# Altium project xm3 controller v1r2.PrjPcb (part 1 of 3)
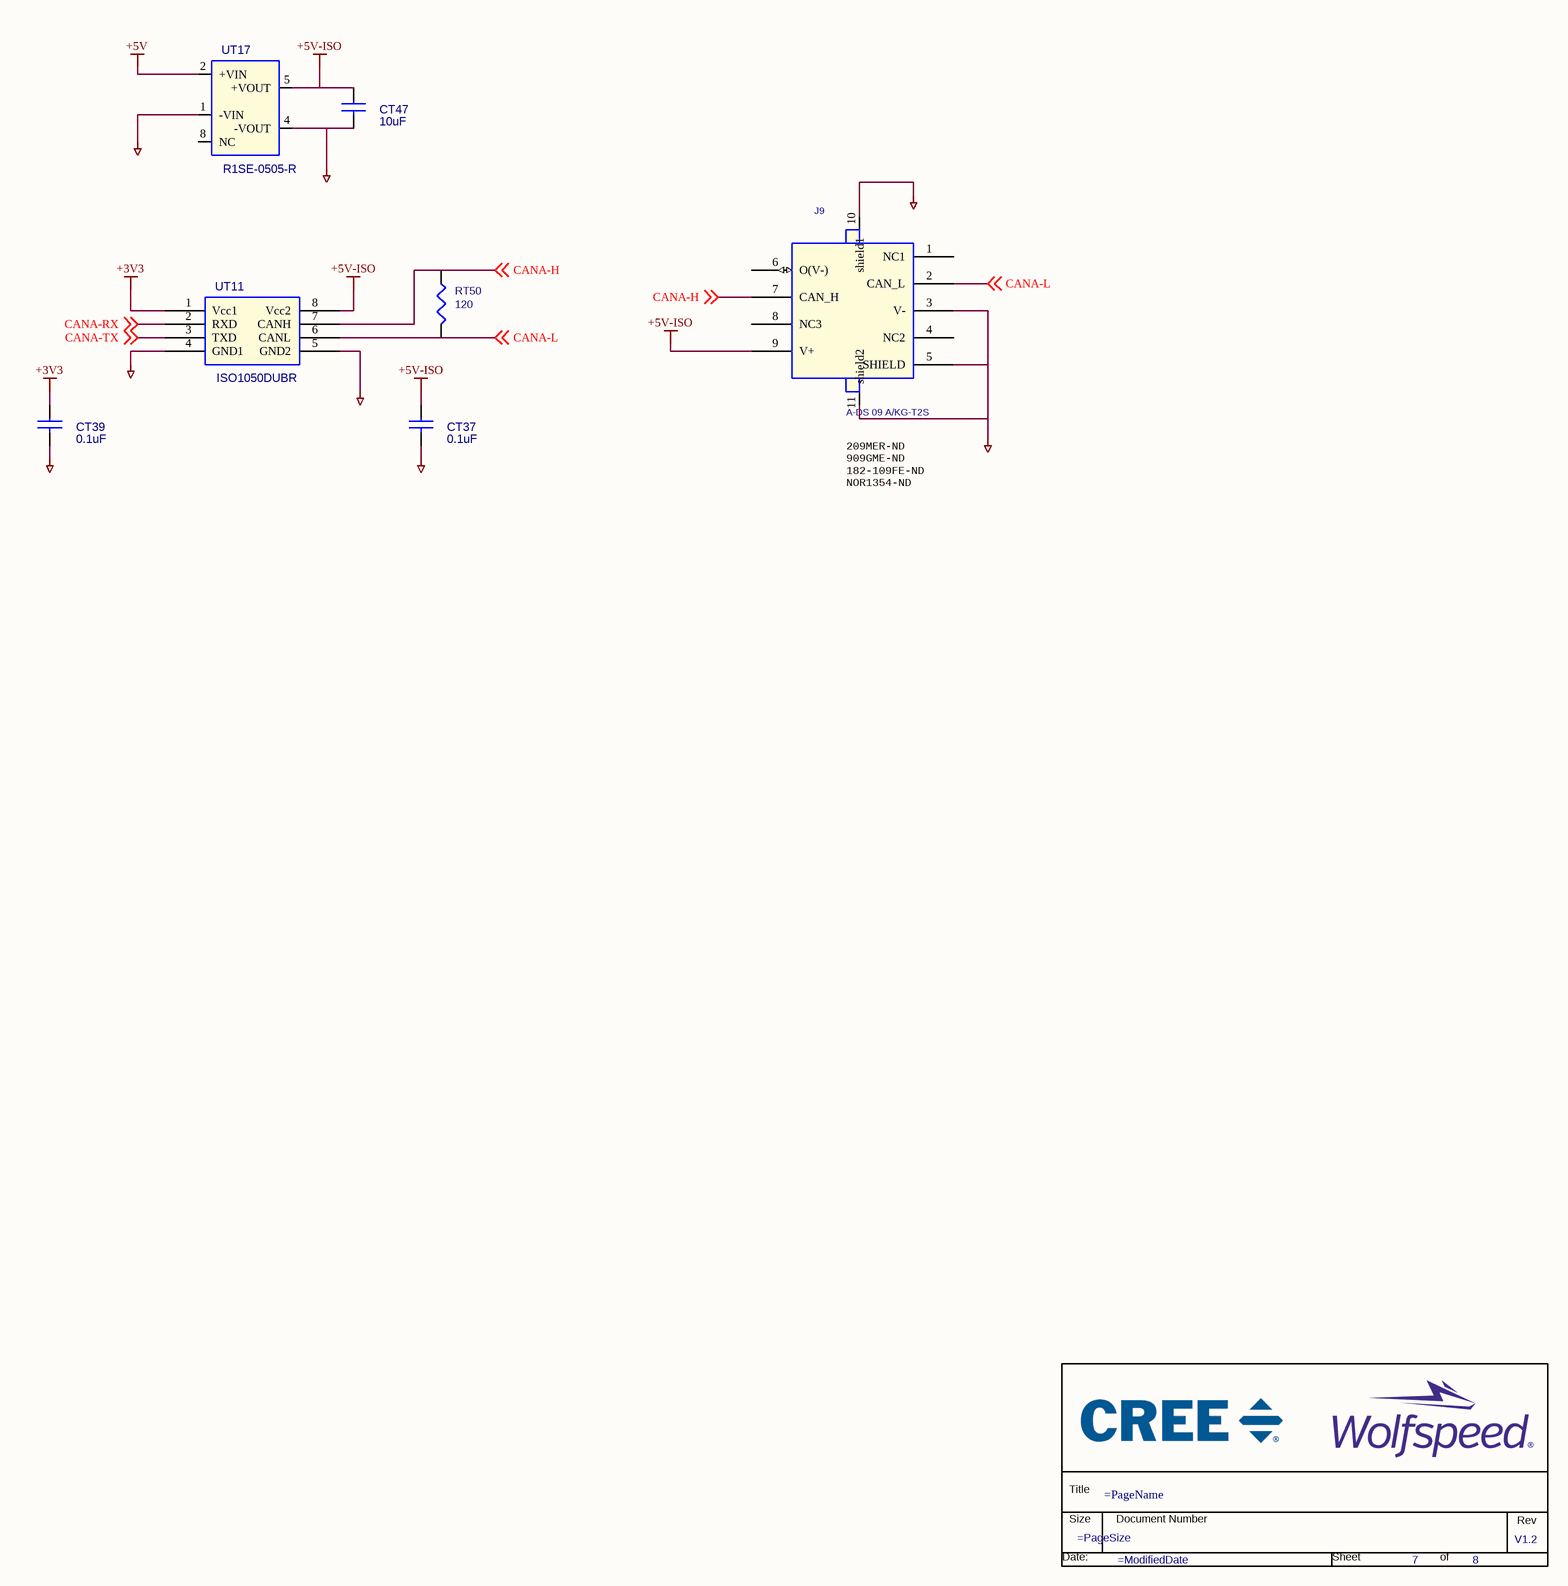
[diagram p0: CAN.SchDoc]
8 sheets, 370 parts. Net scope: global (net labels, ports and power ports of the same name join across sheets).
Board file: XM3-Controller-V1R2-1.PcbDoc
Sheets:
  CAN.SchDoc
  Current Sensors.SchDoc
  Gate Driver Interface.SchDoc
  LAUNCHPAD.SchDoc
  Power Supply.SchDoc
  Revision History.SchDoc
  Temperature Sense.SchDoc
  Voltage Sense.SchDoc

## Sheet CAN.SchDoc: Controller
size 492 x 365 mm; OrgAddr3: USA; Page Create Date: March  8, 1995; OrgName: Wolfspeed; OrgAddr1: 535 W Research Center Blvd.; Page Number: 7; Page Size: A; Comment: DualBrandTitleBlock1; Page Count: 8; OrgAddr2: Fayetteville, AR, 72701; Page Name: CAN; RevCode: V1.2; DsnPath: C:\Users\cnew\Downloads\xm3 controller v1r2-2022-03-14T15-49\xm3 controller v1r2.dsn; SchematicName: SCHEMATIC1; PageName: CAN; PageSize: A; TopSchematic: True

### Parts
(Parts that share a designator on the sheet are numbered #1, #2 ... from top to bottom, then left to right.)
*#1  Page Count: 8  Page Number: 7  RevCode: V1.2  (hidden comment: DualBrandTitleBlock1)  (graphical)
CT37  0.1uF  [CAPC1608X87N]
CT39  0.1uF  [CAPC1608X87N]
CT47  10uF  [CAPC2012X135N]
J9  A-DS 09 A/KG-T2S  [DB9]
RT50  120  [RESC1608X55N]
UT11  ISO1050DUBR  [SMD-8_gull_wing_V2]
UT17  R1SE-0505-R  [8-SMD-5leads]

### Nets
0: CT39.2 UT11.4(GND1) UT17.1(-VIN)
1: CT37.2 CT47.2 J9.3(V-) J9.5(SHIELD) J9.10(shield1) J9.11(shield2) UT11.5(GND2) UT17.4(-VOUT)
+3V3: CT39.1 UT11.1(Vcc1)
+5V: UT17.2(+VIN)
+5V-ISO: CT37.1 CT47.1 J9.9(V+) UT11.8(Vcc2) UT17.5(+VOUT)
CANA-H: J9.7(CAN_H) RT50.1 UT11.7(CANH) ; off-sheet CANA-H
CANA-L: J9.2(CAN_L) RT50.2 UT11.6(CANL) ; off-sheet CANA-L
CANA-RX: UT11.2(RXD) ; off-sheet CANA-RX
CANA-TX: UT11.3(TXD) ; off-sheet CANA-TX

Not connected (* = marked no-connect by the designer): J9 1(NC1) 4(NC2) 6(O(V-)) 8(NC3); UT17 8(NC)

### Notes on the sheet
- (near J9) 209MER-ND
  909GME-ND
  182-109FE-ND
  NOR1354-ND

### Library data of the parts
*#1 = DualBrandTitleBlock1: OrgAddr3: USA; OrgAddr2: Fayetteville, AR, 72701; OrgAddr1: 535 W Research Center Blvd.; OrgName: Wolfspeed; Title: Controller
CT37 = CAP: CAP CER 0.1UF 25V X7R 0603; Part Reference: CT37; Manufacturer PN: C0603C104K3RACTU; Manufacturer: Kemet; PART_NUMBER: TMP-847; Company Part Status: New; CLASS: DISCRETE; Tolerance: 10%; Dielectric Type: Capacitors
CT39 = CAP: CAP CER 0.1UF 25V X7R 0603; Part Reference: CT39; Manufacturer PN: C0603C104K3RACTU; Manufacturer: Kemet; PART_NUMBER: TMP-847; Company Part Status: New; CLASS: DISCRETE; Tolerance: 10%; Dielectric Type: Capacitors
CT47 = CAP: CAP CER 10UF 25V X7S 0805; Part Reference: CT47; Manufacturer: Murata Electronics North America; Manufacturer PN: GRM21BC71E106KE11L; Company Part Status: New; Dielectric Type: Capacitors; Tolerance: 10%; CLASS: DISCRETE
J9 = DSUB - NI CAN Interface_0: CONN D-SUB PLUG 9POS R/A SOLDER; Part Reference: J9; Manufacturer: Assmann WSW Components; Company Part Status: New; CLASS: IO
RT50 = R: RES SMD 120 OHM 5% 1/10W 0603; Part Reference: RT50; PART_NUMBER: TMP-619; Manufacturer: Yageo; Manufacturer PN: RC0603JR-07120RL; Company Part Status: New; Temperature Coefficient: 100ppm/C; Rated Power: 0.1W, 1/10W; CLASS: DISCRETE
UT11 = ISO1050DUB: IC TXRX CAN 5V 8SOP; Part Reference: UT11; PART_NUMBER: TMP-237; Manufacturer: Texas Instruments; Company Part Status: New; Supply Voltage: 3 V - 5.5 V
UT17 = R1se-0505-R: DC/DC CONVERTER 1W 5VIN 5VOUT; Part Reference: UT17; PART_NUMBER: TMP-302; Manufacturer: Recom Power; Company Part Status: New; CLASS: IC

## Sheet Current Sensors.SchDoc: Controller
size 492 x 365 mm; OrgAddr3: USA; Page Create Date: March  8, 1995; OrgName: Wolfspeed; OrgAddr1: 535 W Research Center Blvd.; Page Number: 3; Page Size: A; Comment: DualBrandTitleBlock1; Page Count: 8; OrgAddr2: Fayetteville, AR, 72701; Page Name: Current Sensors; RevCode: V1.2; DsnPath: C:\Users\cnew\Downloads\xm3 controller v1r2-2022-03-14T15-49\xm3 controller v1r2.dsn; SchematicName: SCHEMATIC1; PageName: Current Sensors; PageSize: A; TopSchematic: True
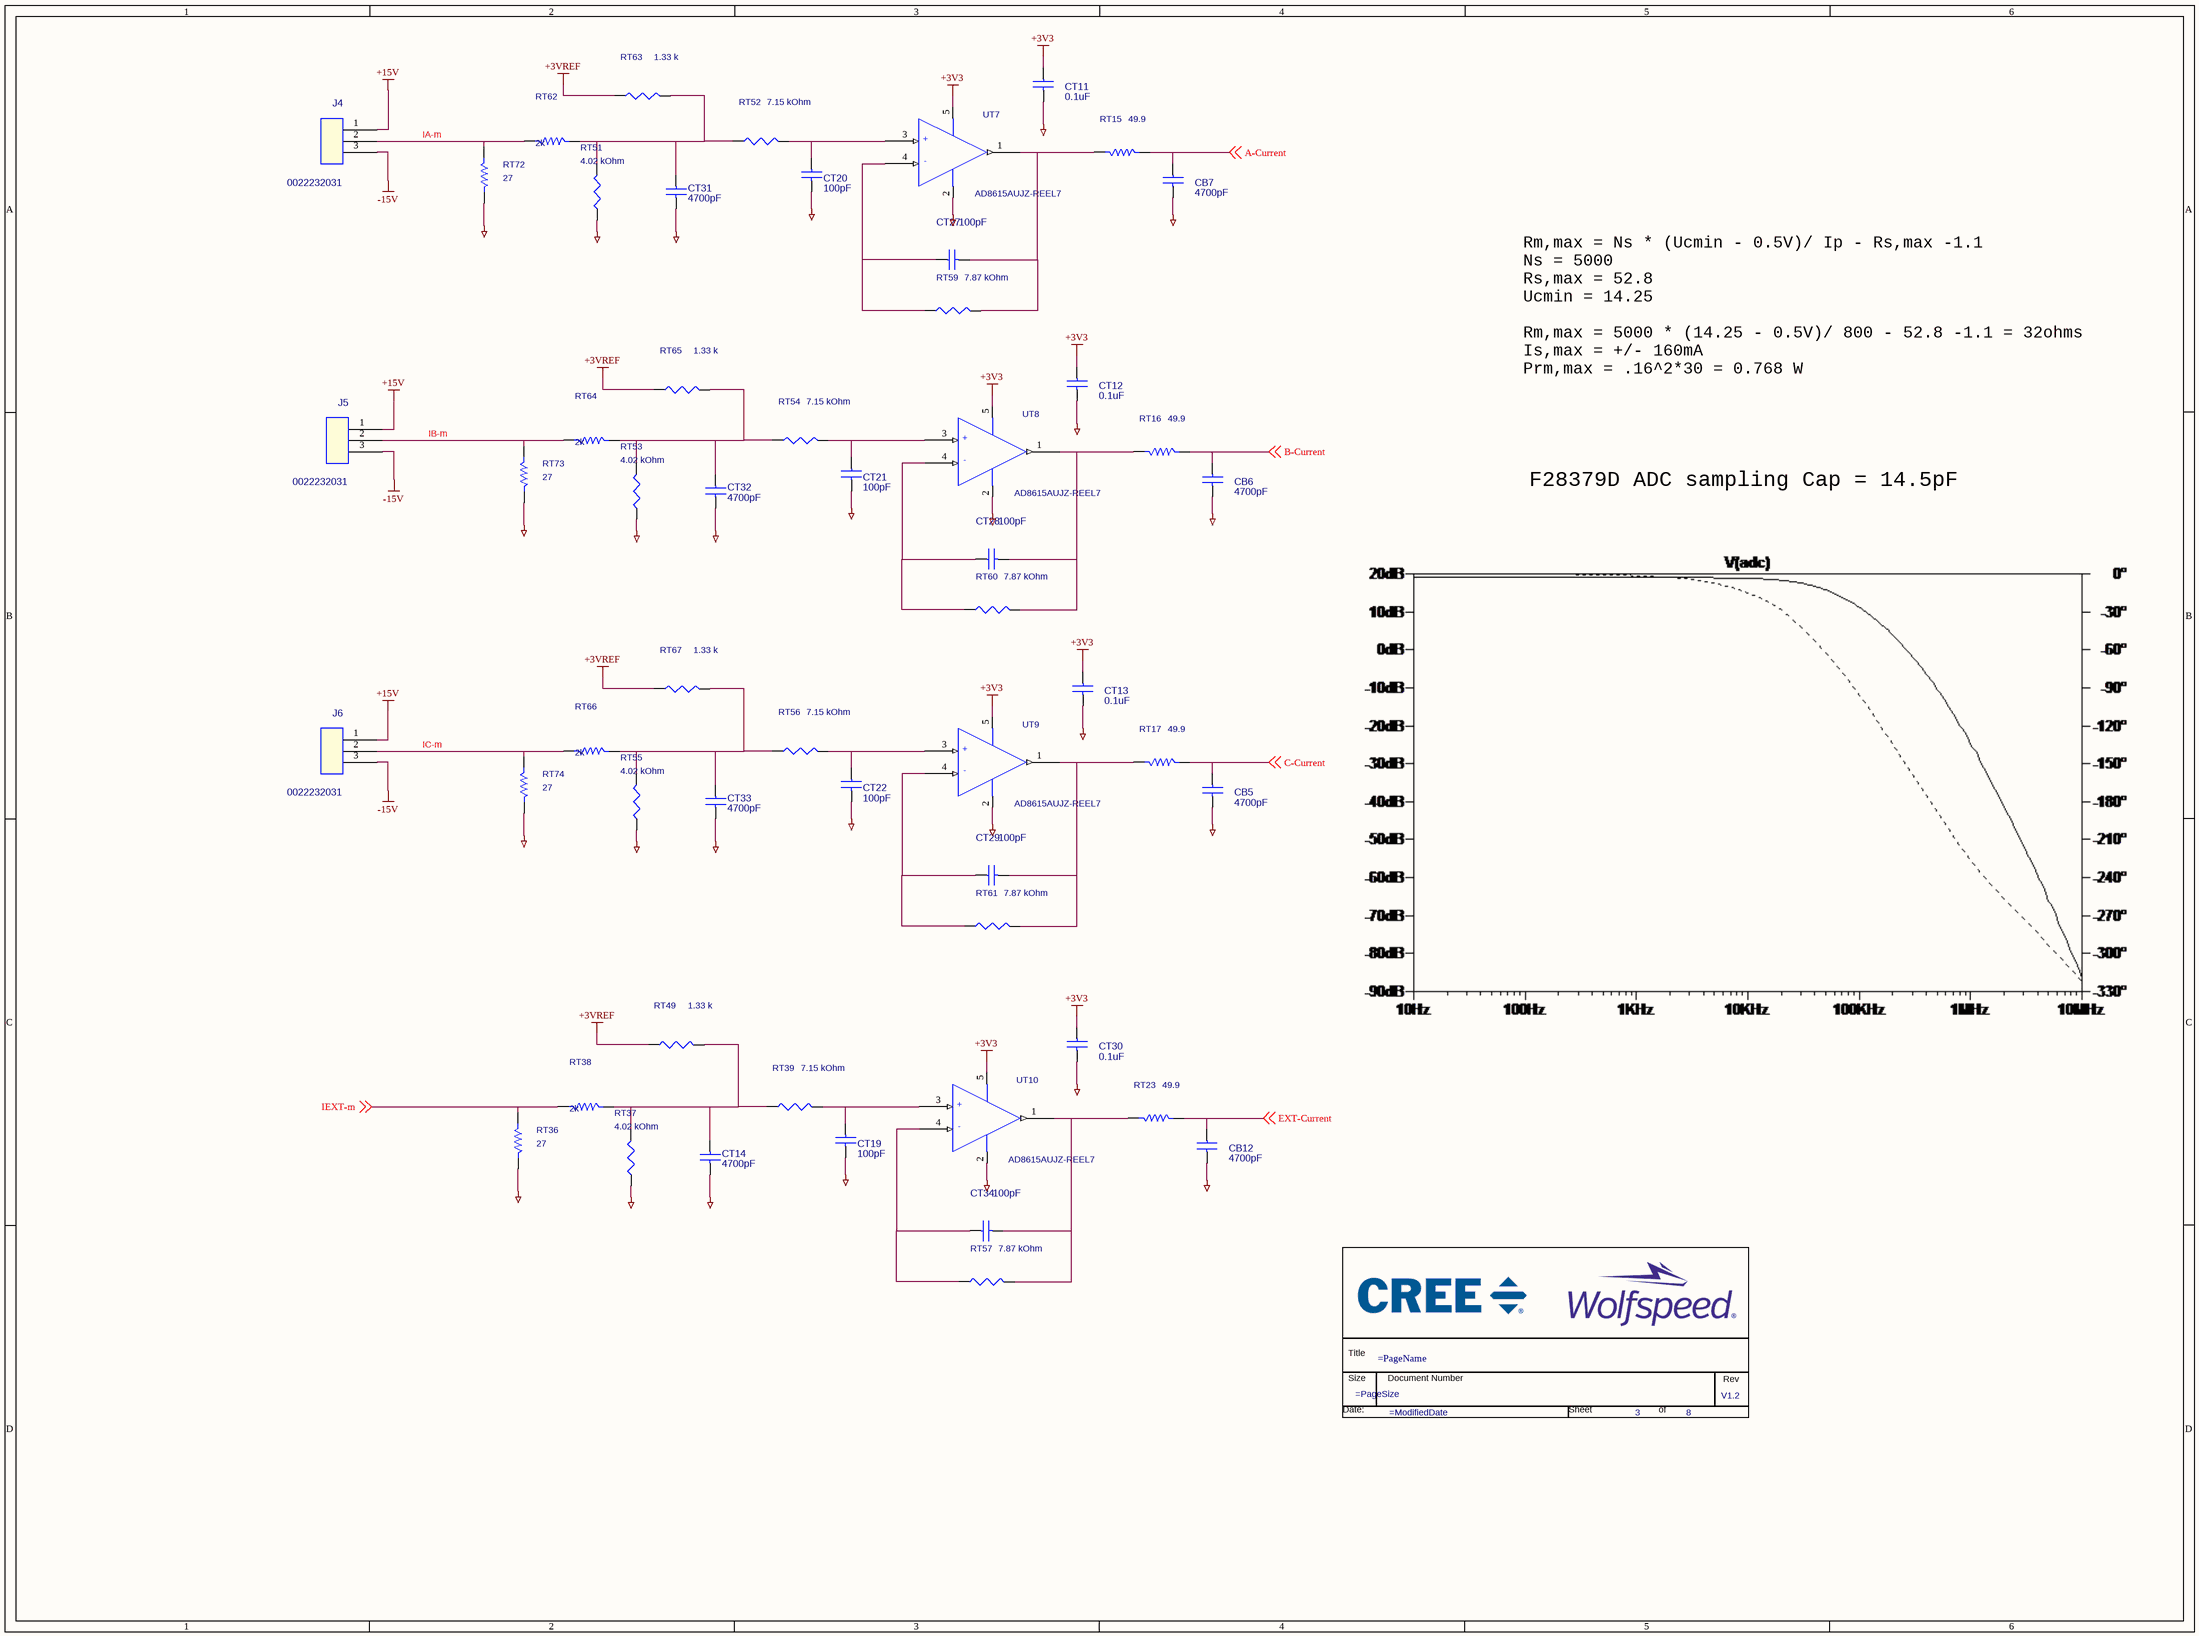
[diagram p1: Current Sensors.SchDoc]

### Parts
(Parts that share a designator on the sheet are numbered #1, #2 ... from top to bottom, then left to right.)
*#2  Page Count: 8  Page Number: 3  RevCode: V1.2  (hidden comment: DualBrandTitleBlock1)  (graphical)
CB5  4700pF  [c_0603]
CB6  4700pF  [c_0603]
CB7  4700pF  [c_0603]
CB12  4700pF  [c_0603]
CT11  0.1uF  [CAPC1608X87N]
CT12  0.1uF  [CAPC1608X87N]
CT13  0.1uF  [CAPC1608X87N]
CT14  4700pF  [c_0603]
CT19  100pF  [CAPC1608X90N]
CT20  100pF  [CAPC1608X90N]
CT21  100pF  [CAPC1608X90N]
CT22  100pF  [CAPC1608X90N]
CT27  100pF  [CAPC1608X90N]
CT28  100pF  [CAPC1608X90N]
CT29  100pF  [CAPC1608X90N]
CT30  0.1uF  [CAPC1608X87N]
CT31  4700pF  [c_0603]
CT32  4700pF  [c_0603]
CT33  4700pF  [c_0603]
CT34  100pF  [CAPC1608X90N]
J4  0022232031  [CON_1x3_vert_lock]
J5  0022232031  [CON_1x3_vert_lock]
J6  0022232031  [CON_1x3_vert_lock]
RT15  49.9  [RESC1608X55N]
RT16  49.9  [RESC1608X55N]
RT17  49.9  [RESC1608X55N]
RT23  49.9  [RESC1608X55N]
RT36  27  [RESC3216X65N]
RT37  4.02 kOhm  [RESC1608X55N]
RT38  2k  [RESC1608X55N]
RT39  7.15 kOhm  [RESC1608X55N]
RT49  1.33 k  [RESC1608X55N]
RT51  4.02 kOhm  [RESC1608X55N]
RT52  7.15 kOhm  [RESC1608X55N]
RT53  4.02 kOhm  [RESC1608X55N]
RT54  7.15 kOhm  [RESC1608X55N]
RT55  4.02 kOhm  [RESC1608X55N]
RT56  7.15 kOhm  [RESC1608X55N]
RT57  7.87 kOhm  [RESC1608X55N]
RT59  7.87 kOhm  [RESC1608X55N]
RT60  7.87 kOhm  [RESC1608X55N]
RT61  7.87 kOhm  [RESC1608X55N]
RT62  2k  [RESC1608X55N]
RT63  1.33 k  [RESC1608X55N]
RT64  2k  [RESC1608X55N]
RT65  1.33 k  [RESC1608X55N]
RT66  2k  [RESC1608X55N]
RT67  1.33 k  [RESC1608X55N]
RT72  27  [RESC3216X65N]
RT73  27  [RESC3216X65N]
RT74  27  [RESC3216X65N]
UT7  AD8615AUJZ-REEL7  [sot23-5_0_95x2_70p_h1_22]
UT8  AD8615AUJZ-REEL7  [sot23-5_0_95x2_70p_h1_22]
UT9  AD8615AUJZ-REEL7  [sot23-5_0_95x2_70p_h1_22]
UT10  AD8615AUJZ-REEL7  [sot23-5_0_95x2_70p_h1_22]

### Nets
0: CB5.2 CB6.2 CB7.2 CB12.2 CT11.2 CT12.2 CT13.2 CT14.2 CT19.2 CT20.2 CT21.2 CT22.2 CT30.2 CT31.2 CT32.2 CT33.2 RT36.2 RT37.1 RT51.1 RT53.1 RT55.1 RT72.2 RT73.2 RT74.2 UT7.2(V-) UT8.2(V-) UT9.2(V-) UT10.2(V-)
+3V3: CT11.1 CT12.1 CT13.1 CT30.1 UT7.5(V+) UT8.5(V+) UT9.5(V+) UT10.5(V+)
+3VREF: RT49.1 RT63.1 RT65.1 RT67.1
+15V: J4.1 J5.1 J6.1
-15V: J4.3 J5.3 J6.3
A-Current: CB7.1 RT15.2 ; off-sheet A-Current
B-Current: CB6.1 RT16.2 ; off-sheet B-Current
C-Current: CB5.1 RT17.2 ; off-sheet C-Current
EXT-Current: CB12.1 RT23.2 ; off-sheet EXT-Current
IA-m: J4.2 RT62.1 RT72.1
IB-m: J5.2 RT64.1 RT73.1
IC-m: J6.2 RT66.1 RT74.1
IEXT-m: RT36.1 RT38.1 ; off-sheet IEXT-m
NetCT14_1: CT14.1 RT37.2 RT38.2 RT39.1 RT49.2
NetCT19_1: CT19.1 RT39.2 UT10.3(IN+)
NetCT20_1: CT20.1 RT52.2 UT7.3(IN+)
NetCT21_1: CT21.1 RT54.2 UT8.3(IN+)
NetCT22_1: CT22.1 RT56.2 UT9.3(IN+)
NetCT27_1: CT27.1 RT59.1 UT7.4(IN-)
NetCT27_2: CT27.2 RT15.1 RT59.2 UT7.1(OUT)
NetCT28_1: CT28.1 RT60.1 UT8.4(IN-)
NetCT28_2: CT28.2 RT16.1 RT60.2 UT8.1(OUT)
NetCT29_1: CT29.1 RT61.1 UT9.4(IN-)
NetCT29_2: CT29.2 RT17.1 RT61.2 UT9.1(OUT)
NetCT31_1: CT31.1 RT51.2 RT52.1 RT62.2 RT63.2
NetCT32_1: CT32.1 RT53.2 RT54.1 RT64.2 RT65.2
NetCT33_1: CT33.1 RT55.2 RT56.1 RT66.2 RT67.2
NetCT34_1: CT34.1 RT57.1 UT10.4(IN-)
NetCT34_2: CT34.2 RT23.1 RT57.2 UT10.1(OUT)

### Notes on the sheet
- Rm,max = Ns * (Ucmin - 0.5V)/ Ip - Rs,max -1.1
  Ns = 5000
  Rs,max = 52.8
  Ucmin = 14.25
- Rm,max = 5000 * (14.25 - 0.5V)/ 800 - 52.8 -1.1 = 32ohms
  Is,max = +/- 160mA
  Prm,max = .16^2*30 = 0.768 W
- F28379D ADC sampling Cap = 14.5pF

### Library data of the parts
*#2 = DualBrandTitleBlock1: as *#1 on sheet CAN
CB5 = CAP: CAP CER 4700PF 25V X7R 0603; Part Reference: CB5; Manufacturer PN: GCM188R71E472KA37D; Manufacturer: Murata Electronics North America; PART_NUMBER: TMP-889; Company Part Status: New; CLASS: DISCRETE; Tolerance: 10%; Dielectric Type: Capacitors
CB6 = CAP: CAP CER 4700PF 25V X7R 0603; Part Reference: CB6; Manufacturer PN: GCM188R71E472KA37D; Manufacturer: Murata Electronics North America; PART_NUMBER: TMP-889; Company Part Status: New; CLASS: DISCRETE; Tolerance: 10%; Dielectric Type: Capacitors
CB7 = CAP: CAP CER 4700PF 25V X7R 0603; Part Reference: CB7; Manufacturer PN: GCM188R71E472KA37D; Manufacturer: Murata Electronics North America; PART_NUMBER: TMP-889; Company Part Status: New; CLASS: DISCRETE; Tolerance: 10%; Dielectric Type: Capacitors
CB12 = CAP: CAP CER 4700PF 25V X7R 0603; Part Reference: CB12; PART_NUMBER: TMP-889; Manufacturer: Murata Electronics North America; Manufacturer PN: GCM188R71E472KA37D; Company Part Status: New; Dielectric Type: Capacitors; Tolerance: 10%; CLASS: DISCRETE
CT11 = CAP: CAP CER 0.1UF 25V X7R 0603; Part Reference: CT11; PART_NUMBER: TMP-847; Manufacturer: Kemet; Manufacturer PN: C0603C104K3RACTU; Company Part Status: New; Dielectric Type: Capacitors; Tolerance: 10%; CLASS: DISCRETE
CT12 = CAP: CAP CER 0.1UF 25V X7R 0603; Part Reference: CT12; PART_NUMBER: TMP-847; Manufacturer: Kemet; Manufacturer PN: C0603C104K3RACTU; Company Part Status: New; Dielectric Type: Capacitors; Tolerance: 10%; CLASS: DISCRETE
CT13 = CAP: CAP CER 0.1UF 25V X7R 0603; Part Reference: CT13; PART_NUMBER: TMP-847; Manufacturer: Kemet; Manufacturer PN: C0603C104K3RACTU; Company Part Status: New; Dielectric Type: Capacitors; Tolerance: 10%; CLASS: DISCRETE
CT14 = CAP: CAP CER 4700PF 25V X7R 0603; Part Reference: CT14; PART_NUMBER: TMP-889; Manufacturer: Murata Electronics North America; Manufacturer PN: GCM188R71E472KA37D; Company Part Status: New; Dielectric Type: Capacitors; Tolerance: 10%; CLASS: DISCRETE
CT19 = CAP: CAP CER 100PF 50V 5% NP0 0603; Part Reference: CT19; PART_NUMBER: TMP-455; Manufacturer: Samsung Electro-Mechanics America, Inc; Manufacturer PN: CL10C101JB8NNNC; Company Part Status: New; Dielectric Type: Capacitors; Temperature Coefficient: C0G, NP0; CLASS: DISCRETE
CT20 = CAP: CAP CER 100PF 50V 5% NP0 0603; Part Reference: CT20; Manufacturer PN: CL10C101JB8NNNC; Manufacturer: Samsung Electro-Mechanics America, Inc; PART_NUMBER: TMP-455; Company Part Status: New; CLASS: DISCRETE; Temperature Coefficient: C0G, NP0; Dielectric Type: Capacitors
CT21 = CAP: CAP CER 100PF 50V 5% NP0 0603; Part Reference: CT21; Manufacturer PN: CL10C101JB8NNNC; Manufacturer: Samsung Electro-Mechanics America, Inc; PART_NUMBER: TMP-455; Company Part Status: New; CLASS: DISCRETE; Temperature Coefficient: C0G, NP0; Dielectric Type: Capacitors
CT22 = CAP: CAP CER 100PF 50V 5% NP0 0603; Part Reference: CT22; Manufacturer PN: CL10C101JB8NNNC; Manufacturer: Samsung Electro-Mechanics America, Inc; PART_NUMBER: TMP-455; Company Part Status: New; CLASS: DISCRETE; Temperature Coefficient: C0G, NP0; Dielectric Type: Capacitors
CT27 = CAP: CAP CER 100PF 50V 5% NP0 0603; Part Reference: CT27; PART_NUMBER: TMP-455; Manufacturer: Samsung Electro-Mechanics America, Inc; Manufacturer PN: CL10C101JB8NNNC; Company Part Status: New; Dielectric Type: Capacitors; Temperature Coefficient: C0G, NP0; CLASS: DISCRETE
CT28 = CAP: CAP CER 100PF 50V 5% NP0 0603; Part Reference: CT28; PART_NUMBER: TMP-455; Manufacturer: Samsung Electro-Mechanics America, Inc; Manufacturer PN: CL10C101JB8NNNC; Company Part Status: New; Dielectric Type: Capacitors; Temperature Coefficient: C0G, NP0; CLASS: DISCRETE
CT29 = CAP: CAP CER 100PF 50V 5% NP0 0603; Part Reference: CT29; PART_NUMBER: TMP-455; Manufacturer: Samsung Electro-Mechanics America, Inc; Manufacturer PN: CL10C101JB8NNNC; Company Part Status: New; Dielectric Type: Capacitors; Temperature Coefficient: C0G, NP0; CLASS: DISCRETE
CT30 = CAP: CAP CER 0.1UF 25V X7R 0603; Part Reference: CT30; Manufacturer PN: C0603C104K3RACTU; Manufacturer: Kemet; PART_NUMBER: TMP-847; Company Part Status: New; CLASS: DISCRETE; Tolerance: 10%; Dielectric Type: Capacitors
CT31 = CAP: CAP CER 4700PF 25V X7R 0603; Part Reference: CT31; Manufacturer PN: GCM188R71E472KA37D; Manufacturer: Murata Electronics North America; PART_NUMBER: TMP-889; Company Part Status: New; CLASS: DISCRETE; Tolerance: 10%; Dielectric Type: Capacitors
CT32 = CAP: CAP CER 4700PF 25V X7R 0603; Part Reference: CT32; Manufacturer PN: GCM188R71E472KA37D; Manufacturer: Murata Electronics North America; PART_NUMBER: TMP-889; Company Part Status: New; CLASS: DISCRETE; Tolerance: 10%; Dielectric Type: Capacitors
CT33 = CAP: CAP CER 4700PF 25V X7R 0603; Part Reference: CT33; Manufacturer PN: GCM188R71E472KA37D; Manufacturer: Murata Electronics North America; PART_NUMBER: TMP-889; Company Part Status: New; CLASS: DISCRETE; Tolerance: 10%; Dielectric Type: Capacitors
CT34 = CAP: CAP CER 100PF 50V 5% NP0 0603; Part Reference: CT34; Manufacturer PN: CL10C101JB8NNNC; Manufacturer: Samsung Electro-Mechanics America, Inc; PART_NUMBER: TMP-455; Company Part Status: New; CLASS: DISCRETE; Temperature Coefficient: C0G, NP0; Dielectric Type: Capacitors
J4 = CON3: CONN HEADER 3POS .100 VERT TIN; Part Reference: J4; Manufacturer: Molex, LLC; PART_NUMBER: TMP-626; Company Part Status: New; CLASS: IO
J5 = CON3: CONN HEADER 3POS .100 VERT TIN; Part Reference: J5; Manufacturer: Molex, LLC; PART_NUMBER: TMP-626; Company Part Status: New; CLASS: IO
J6 = CON3: CONN HEADER 3POS .100 VERT TIN; Part Reference: J6; Manufacturer: Molex, LLC; PART_NUMBER: TMP-626; Company Part Status: New; CLASS: IO
RT15 = RES_Dup1: RES SMD 49.9 OHM 1% 1/10W 0603; Part Reference: RT15; Manufacturer PN: ERJ-3EKF49R9V; Manufacturer: Panasonic Electronic Components; Company Part Status: New; CLASS: DISCRETE; Rated Power: 0.1W, 1/10W; Temperature Coefficient: 100ppm/C
RT16 = RES_Dup1: RES SMD 49.9 OHM 1% 1/10W 0603; Part Reference: RT16; Manufacturer PN: ERJ-3EKF49R9V; Manufacturer: Panasonic Electronic Components; Company Part Status: New; CLASS: DISCRETE; Rated Power: 0.1W, 1/10W; Temperature Coefficient: 100ppm/C
RT17 = RES_Dup1: RES SMD 49.9 OHM 1% 1/10W 0603; Part Reference: RT17; Manufacturer PN: ERJ-3EKF49R9V; Manufacturer: Panasonic Electronic Components; Company Part Status: New; CLASS: DISCRETE; Rated Power: 0.1W, 1/10W; Temperature Coefficient: 100ppm/C
RT23 = RES_Dup1: RES SMD 49.9 OHM 1% 1/10W 0603; Part Reference: RT23; Manufacturer: Panasonic Electronic Components; Manufacturer PN: ERJ-3EKF49R9V; Company Part Status: New; Temperature Coefficient: 100ppm/C; Rated Power: 0.1W, 1/10W; CLASS: DISCRETE
RT36 = RES_Dup1: RES SMD 27 OHM 0.5% 1W 1206; Part Reference: RT36; Company Part Status: New; Manufacturer PN: HRG3216Q-27R0-D-T1; Manufacturer: Susumu; CLASS: DISCRETE; Temperature Coefficient: 50ppm/C
RT37 = R: RES SMD 4.02KOHM 0.1% 1/10W 0603; Part Reference: RT37; Manufacturer PN: ERA-3AEB4021V; Manufacturer: Panasonic Electronic Components; Company Part Status: New; CLASS: DISCRETE; Rated Power: 0.1W, 1/10W; Temperature Coefficient: 25ppm/C
RT38 = RES_Dup1: RES SMD 2K OHM 1% 1/10W 0603; Part Reference: RT38; Manufacturer: Yageo; Manufacturer PN: RC0603FR-072KL; Company Part Status: New; Temperature Coefficient: 100ppm/C; Rated Power: 0.1W, 1/10W; CLASS: DISCRETE
RT39 = R: RES 7.15K OHM 1% 1/10W 0603; Part Reference: RT39; Manufacturer: Stackpole Electronics Inc.; Manufacturer PN: RMCF0603FT7K15; Company Part Status: New; Temperature Coefficient: 100ppm/C; Rated Power: 0.1W, 1/10W; CLASS: DISCRETE
RT49 = R: RES 1.33K OHM 1% 1/10W 0603; Part Reference: RT49; Manufacturer PN: RMCF0603FT1K33; Manufacturer: Stackpole Electronics Inc.; Company Part Status: New; CLASS: DISCRETE; Rated Power: 0.1W, 1/10W; Temperature Coefficient: 100ppm/C
RT51 = R: RES SMD 4.02KOHM 0.1% 1/10W 0603; Part Reference: RT51; Manufacturer: Panasonic Electronic Components; Manufacturer PN: ERA-3AEB4021V; Company Part Status: New; Temperature Coefficient: 25ppm/C; Rated Power: 0.1W, 1/10W; CLASS: DISCRETE
RT52 = R: RES 7.15K OHM 1% 1/10W 0603; Part Reference: RT52; Manufacturer PN: RMCF0603FT7K15; Manufacturer: Stackpole Electronics Inc.; Company Part Status: New; CLASS: DISCRETE; Rated Power: 0.1W, 1/10W; Temperature Coefficient: 100ppm/C
RT53 = R: RES SMD 4.02KOHM 0.1% 1/10W 0603; Part Reference: RT53; Manufacturer: Panasonic Electronic Components; Manufacturer PN: ERA-3AEB4021V; Company Part Status: New; Temperature Coefficient: 25ppm/C; Rated Power: 0.1W, 1/10W; CLASS: DISCRETE
RT54 = R: RES 7.15K OHM 1% 1/10W 0603; Part Reference: RT54; Manufacturer PN: RMCF0603FT7K15; Manufacturer: Stackpole Electronics Inc.; Company Part Status: New; CLASS: DISCRETE; Rated Power: 0.1W, 1/10W; Temperature Coefficient: 100ppm/C
RT55 = R: RES SMD 4.02KOHM 0.1% 1/10W 0603; Part Reference: RT55; Manufacturer: Panasonic Electronic Components; Manufacturer PN: ERA-3AEB4021V; Company Part Status: New; Temperature Coefficient: 25ppm/C; Rated Power: 0.1W, 1/10W; CLASS: DISCRETE
RT56 = R: RES 7.15K OHM 1% 1/10W 0603; Part Reference: RT56; Manufacturer PN: RMCF0603FT7K15; Manufacturer: Stackpole Electronics Inc.; Company Part Status: New; CLASS: DISCRETE; Rated Power: 0.1W, 1/10W; Temperature Coefficient: 100ppm/C
RT57 = R: RES SMD 7.87K OHM 1% 1/10W 0603; Part Reference: RT57; Manufacturer PN: RC0603FR-077K87L; Manufacturer: Yageo; Company Part Status: New; CLASS: DISCRETE; Rated Power: 0.1W, 1/10W; Temperature Coefficient: 100ppm/C
RT59 = R: RES SMD 7.87K OHM 1% 1/10W 0603; Part Reference: RT59; Manufacturer: Yageo; Manufacturer PN: RC0603FR-077K87L; Company Part Status: New; Temperature Coefficient: 100ppm/C; Rated Power: 0.1W, 1/10W; CLASS: DISCRETE
RT60 = R: RES SMD 7.87K OHM 1% 1/10W 0603; Part Reference: RT60; Manufacturer: Yageo; Manufacturer PN: RC0603FR-077K87L; Company Part Status: New; Temperature Coefficient: 100ppm/C; Rated Power: 0.1W, 1/10W; CLASS: DISCRETE
RT61 = R: RES SMD 7.87K OHM 1% 1/10W 0603; Part Reference: RT61; Manufacturer: Yageo; Manufacturer PN: RC0603FR-077K87L; Company Part Status: New; Temperature Coefficient: 100ppm/C; Rated Power: 0.1W, 1/10W; CLASS: DISCRETE
RT62 = RES_Dup1: RES SMD 2K OHM 1% 1/10W 0603; Part Reference: RT62; Manufacturer: Yageo; Manufacturer PN: RC0603FR-072KL; Company Part Status: New; Temperature Coefficient: 100ppm/C; Rated Power: 0.1W, 1/10W; CLASS: DISCRETE
RT63 = R: RES 1.33K OHM 1% 1/10W 0603; Part Reference: RT63; Manufacturer: Stackpole Electronics Inc.; Manufacturer PN: RMCF0603FT1K33; Company Part Status: New; Temperature Coefficient: 100ppm/C; Rated Power: 0.1W, 1/10W; CLASS: DISCRETE
RT64 = RES_Dup1: RES SMD 2K OHM 1% 1/10W 0603; Part Reference: RT64; Manufacturer: Yageo; Manufacturer PN: RC0603FR-072KL; Company Part Status: New; Temperature Coefficient: 100ppm/C; Rated Power: 0.1W, 1/10W; CLASS: DISCRETE
RT65 = R: RES 1.33K OHM 1% 1/10W 0603; Part Reference: RT65; Manufacturer: Stackpole Electronics Inc.; Manufacturer PN: RMCF0603FT1K33; Company Part Status: New; Temperature Coefficient: 100ppm/C; Rated Power: 0.1W, 1/10W; CLASS: DISCRETE
RT66 = RES_Dup1: RES SMD 2K OHM 1% 1/10W 0603; Part Reference: RT66; Manufacturer: Yageo; Manufacturer PN: RC0603FR-072KL; Company Part Status: New; Temperature Coefficient: 100ppm/C; Rated Power: 0.1W, 1/10W; CLASS: DISCRETE
RT67 = R: RES 1.33K OHM 1% 1/10W 0603; Part Reference: RT67; Manufacturer: Stackpole Electronics Inc.; Manufacturer PN: RMCF0603FT1K33; Company Part Status: New; Temperature Coefficient: 100ppm/C; Rated Power: 0.1W, 1/10W; CLASS: DISCRETE
RT72 = RES_Dup1: RES SMD 27 OHM 0.5% 1W 1206; Part Reference: RT72; Company Part Status: New; Manufacturer PN: HRG3216Q-27R0-D-T1; Manufacturer: Susumu; CLASS: DISCRETE; Temperature Coefficient: 50ppm/C
RT73 = RES_Dup1: RES SMD 27 OHM 0.5% 1W 1206; Part Reference: RT73; Company Part Status: New; Manufacturer: Susumu; Manufacturer PN: HRG3216Q-27R0-D-T1; Temperature Coefficient: 50ppm/C; CLASS: DISCRETE
RT74 = RES_Dup1: RES SMD 27 OHM 0.5% 1W 1206; Part Reference: RT74; Company Part Status: New; Manufacturer: Susumu; Manufacturer PN: HRG3216Q-27R0-D-T1; Temperature Coefficient: 50ppm/C; CLASS: DISCRETE
UT7 = AD8615_Dup1: IC OPAMP GP 24MHZ RRO TSOT23-5; Part Reference: UT7; Manufacturer: Analog Devices Inc.; Company Part Status: New; Supply Voltage: 2.7 V - 5.5 V, 1.35 V - 2.75 V
UT8 = AD8615_Dup1: IC OPAMP GP 24MHZ RRO TSOT23-5; Part Reference: UT8; Manufacturer: Analog Devices Inc.; Company Part Status: New; Supply Voltage: 2.7 V - 5.5 V, 1.35 V - 2.75 V
UT9 = AD8615_Dup1: IC OPAMP GP 24MHZ RRO TSOT23-5; Part Reference: UT9; Manufacturer: Analog Devices Inc.; Company Part Status: New; Supply Voltage: 2.7 V - 5.5 V, 1.35 V - 2.75 V
UT10 = AD8615_Dup1: IC OPAMP GP 24MHZ RRO TSOT23-5; Part Reference: UT10; Manufacturer: Analog Devices Inc.; Company Part Status: New; Supply Voltage: 2.7 V - 5.5 V, 1.35 V - 2.75 V

## Sheet Gate Driver Interface.SchDoc: Controller
size 492 x 365 mm; OrgAddr3: USA; Page Create Date: March  8, 1995; OrgName: Wolfspeed; OrgAddr1: 535 W Research Center Blvd.; Page Number: 2; Page Size: A; Comment: DualBrandTitleBlock1; Page Count: 8; OrgAddr2: Fayetteville, AR, 72701; Page Name: Gate Driver Interface; RevCode: V1.2; DsnPath: C:\Users\cnew\Downloads\xm3 controller v1r2-2022-03-14T15-49\xm3 controller v1r2.dsn; SchematicName: SCHEMATIC1; PageName: Gate Driver Interface; PageSize: A; TopSchematic: True
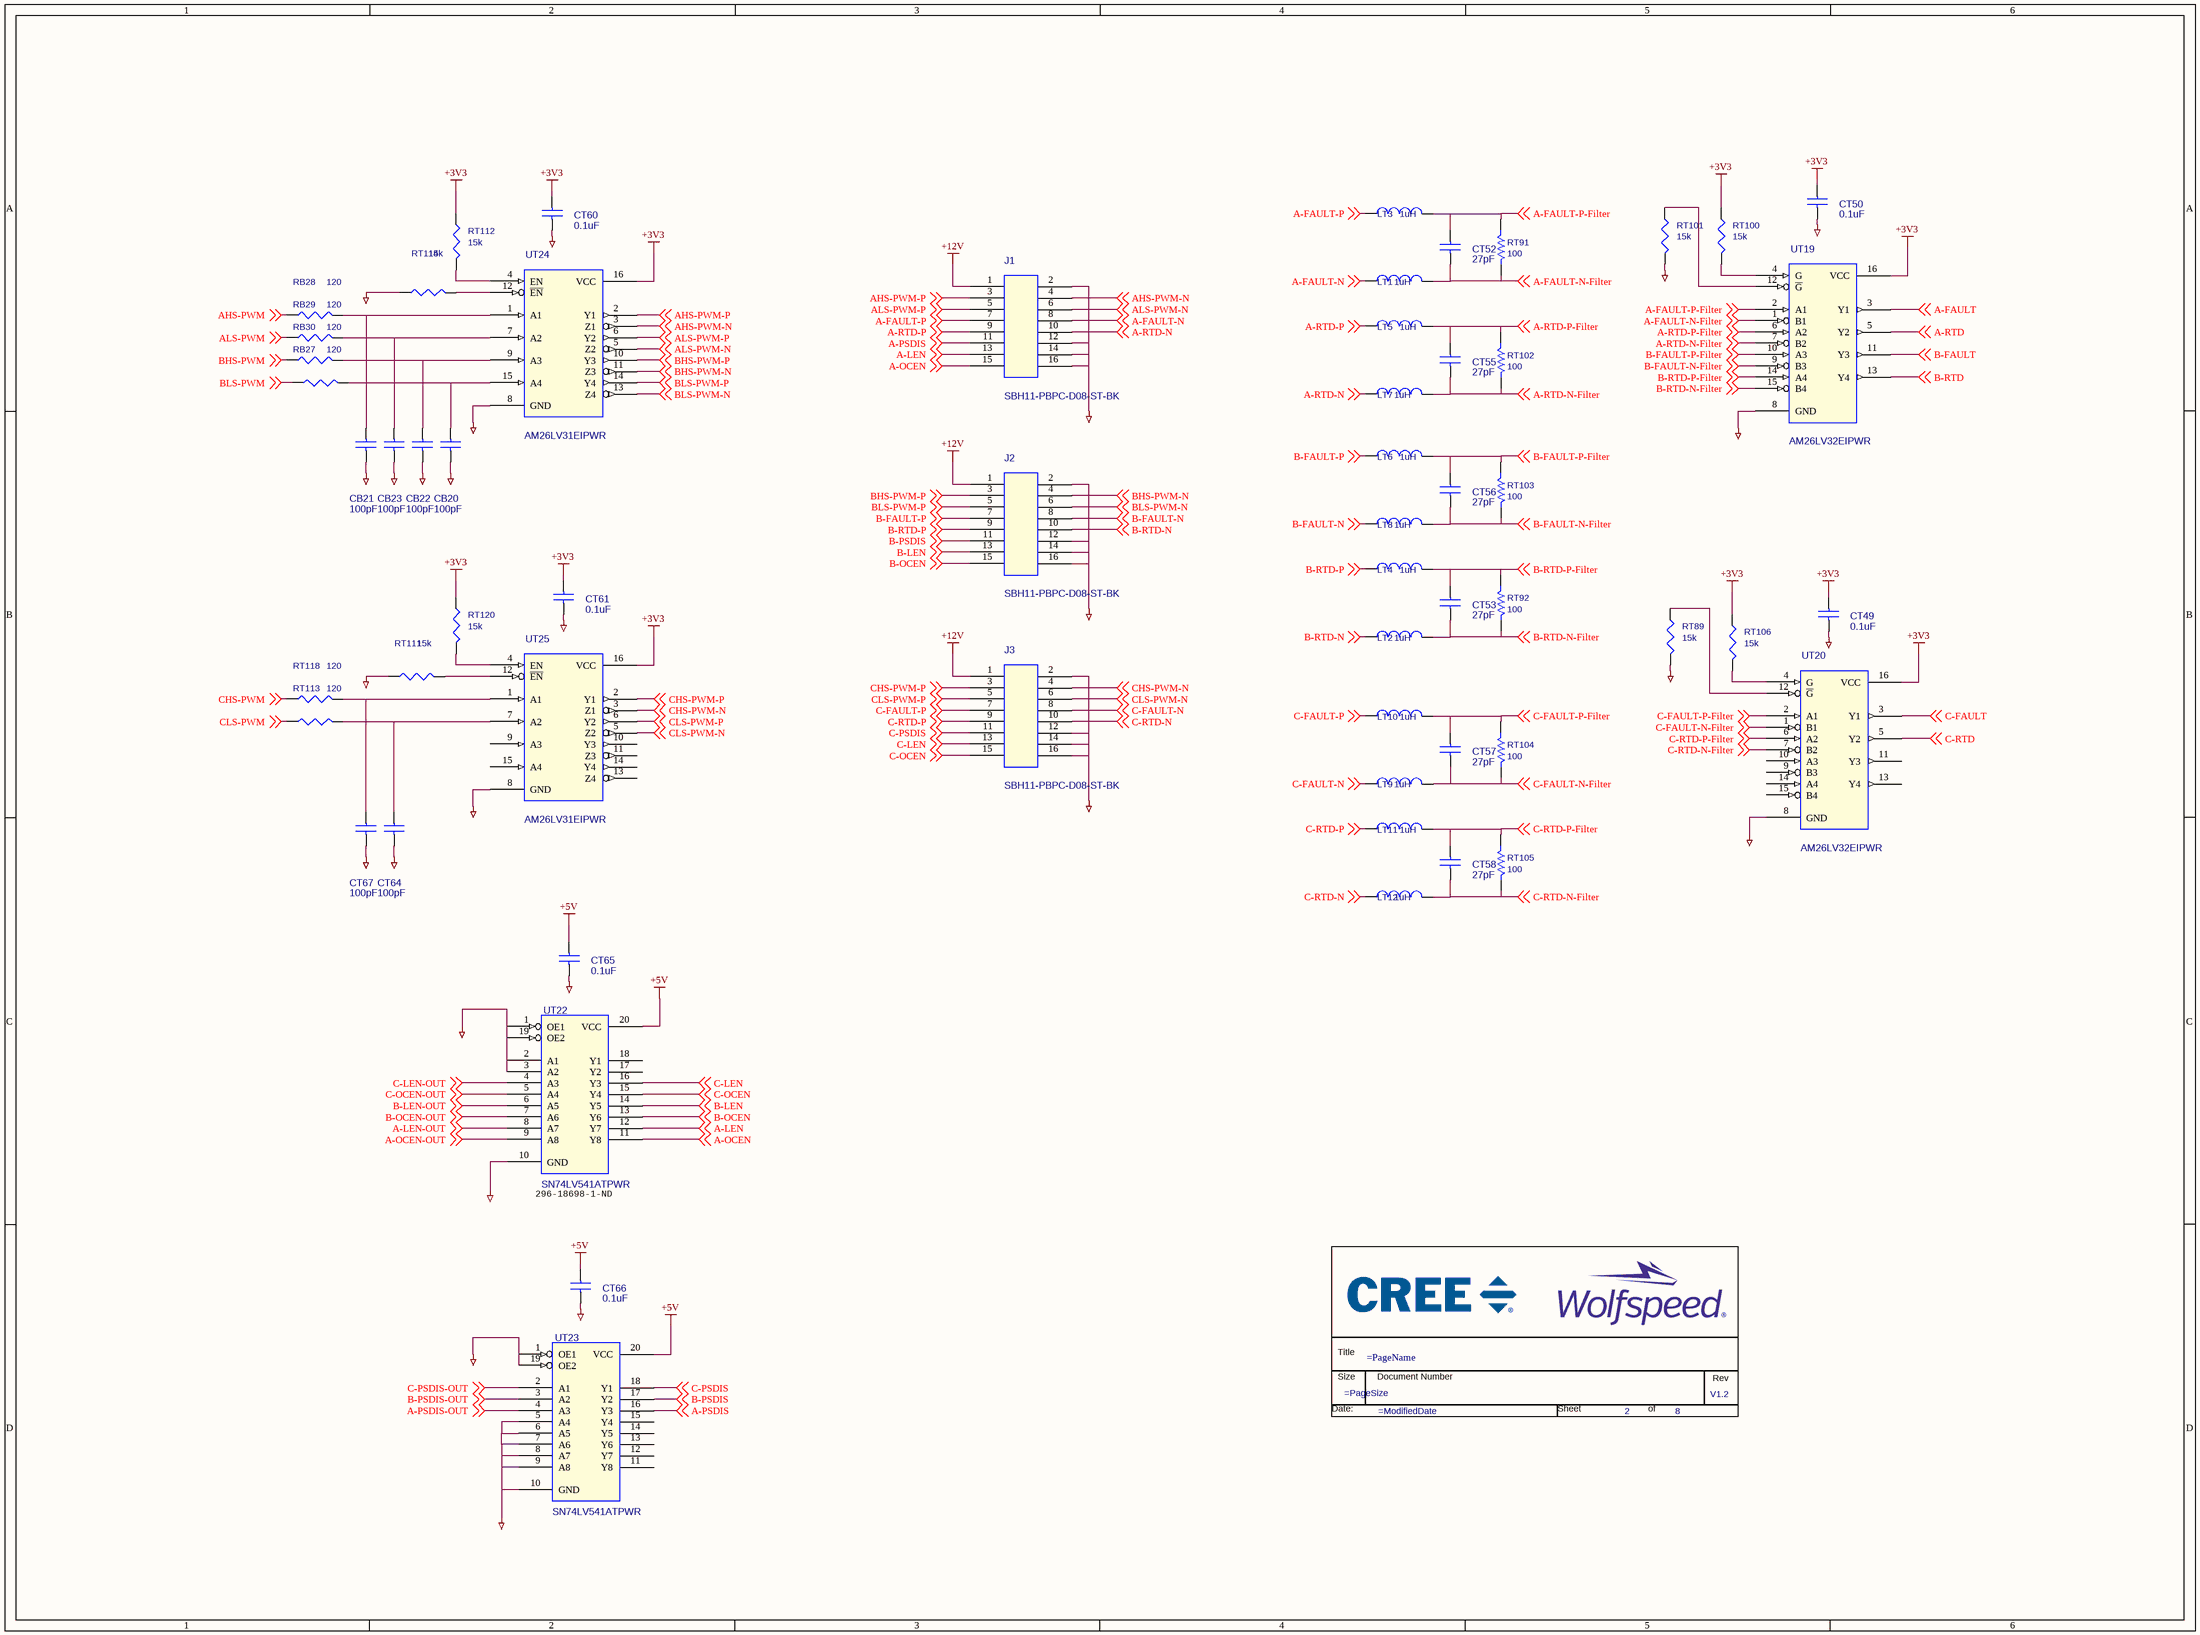
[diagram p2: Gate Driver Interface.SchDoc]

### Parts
(Parts that share a designator on the sheet are numbered #1, #2 ... from top to bottom, then left to right.)
*#3  Page Count: 8  Page Number: 2  RevCode: V1.2  (hidden comment: DualBrandTitleBlock1)  (graphical)
CB20  100pF  [CAPC1608X90N]
CB21  100pF  [CAPC1608X90N]
CB22  100pF  [CAPC1608X90N]
CB23  100pF  [CAPC1608X90N]
CT49  0.1uF  [CAPC1608X87N]
CT50  0.1uF  [CAPC1608X87N]
CT52  27pF  [CAPC1608X90N]
CT53  27pF  [CAPC1608X90N]
CT55  27pF  [CAPC1608X90N]
CT56  27pF  [CAPC1608X90N]
CT57  27pF  [CAPC1608X90N]
CT58  27pF  [CAPC1608X90N]
CT60  0.1uF  [CAPC1608X87N]
CT61  0.1uF  [CAPC1608X87N]
CT64  100pF  [CAPC1608X90N]
CT65  0.1uF  [CAPC1608X87N]
CT66  0.1uF  [CAPC1608X87N]
CT67  100pF  [CAPC1608X90N]
J1  SBH11-PBPC-D08-ST-BK  [CON_2x8_shrouded_corrected]
J2  SBH11-PBPC-D08-ST-BK  [CON_2x8_shrouded_corrected]
J3  SBH11-PBPC-D08-ST-BK  [CON_2x8_shrouded_corrected]
LT1  1uH  [l_0805]
LT2  1uH  [l_0805]
LT3  1uH  [l_0805]
LT4  1uH  [l_0805]
LT5  1uH  [l_0805]
LT6  1uH  [l_0805]
LT7  1uH  [l_0805]
LT8  1uH  [l_0805]
LT9  1uH  [l_0805]
LT10  1uH  [l_0805]
LT11  1uH  [l_0805]
LT12  1uH  [l_0805]
RB27  120  [RESC1608X55N]
RB28  120  [RESC1608X55N]
RB29  120  [RESC1608X55N]
RB30  120  [RESC1608X55N]
RT89  15k  [RESC1608X55N]
RT91  100  [RESC1608X55N]
RT92  100  [RESC1608X55N]
RT100  15k  [RESC1608X55N]
RT101  15k  [RESC1608X55N]
RT102  100  [RESC1608X55N]
RT103  100  [RESC1608X55N]
RT104  100  [RESC1608X55N]
RT105  100  [RESC1608X55N]
RT106  15k  [RESC1608X55N]
RT111  15k  [RESC1608X55N]
RT112  15k  [RESC1608X55N]
RT113  120  [RESC1608X55N]
RT114  15k  [RESC1608X55N]
RT118  120  [RESC1608X55N]
RT120  15k  [RESC1608X55N]
UT19  AM26LV32EIPWR  [TSSOP-16P_P65MM]
UT20  AM26LV32EIPWR  [TSSOP-16P_P65MM]
UT22  SN74LV541ATPWR  [SOP65P640X120-20AN]
UT23  SN74LV541ATPWR  [SOP65P640X120-20AN]
UT24  AM26LV31EIPWR  [TSSOP-16P_P65MM]
UT25  AM26LV31EIPWR  [TSSOP-16P_P65MM]

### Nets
0: CB20.2 CB21.2 CB22.2 CB23.2 CT49.2 CT50.2 CT60.2 CT61.2 CT64.2 CT65.2 CT66.2 CT67.2 J1.2 J1.12 J1.14 J1.16 J2.2 J2.12 J2.14 J2.16 J3.2 J3.12 J3.14 J3.16 RT89.2 RT101.2 RT111.1 RT114.1 UT19.8(GND) UT20.8(GND) UT22.1(OE1) UT22.2(A1) UT22.3(A2) UT22.10(GND) UT22.19(OE2) UT23.1(OE1) UT23.5(A4) UT23.6(A5) UT23.7(A6) UT23.8(A7) UT23.9(A8) UT23.10(GND) UT23.19(OE2) UT24.8(GND) UT25.8(GND)
+3V3: CT49.1 CT50.1 CT60.1 CT61.1 RT100.1 RT106.1 RT112.1 RT120.1 UT19.16(VCC) UT20.16(VCC) UT24.16(VCC) UT25.16(VCC)
+5V: CT65.1 CT66.1 UT22.20(VCC) UT23.20(VCC)
+12V: J1.1 J2.1 J3.1
A-FAULT: UT19.3(Y1) ; off-sheet A-FAULT
A-FAULT-N: J1.8 LT1.1 ; off-sheet A-FAULT-N
A-FAULT-N-Filter: CT52.2 LT1.2 RT91.2 UT19.1(B1) ; off-sheet A-FAULT-N-Filter
A-FAULT-P: J1.7 LT3.1 ; off-sheet A-FAULT-P
A-FAULT-P-Filter: CT52.1 LT3.2 RT91.1 UT19.2(A1) ; off-sheet A-FAULT-P-Filter
A-LEN: J1.13 UT22.12(Y7) ; off-sheet A-LEN
A-LEN-OUT: UT22.8(A7) ; off-sheet A-LEN-OUT
A-OCEN: J1.15 UT22.11(Y8) ; off-sheet A-OCEN
A-OCEN-OUT: UT22.9(A8) ; off-sheet A-OCEN-OUT
A-PSDIS: J1.11 UT23.16(Y3) ; off-sheet A-PSDIS
A-PSDIS-OUT: UT23.4(A3) ; off-sheet A-PSDIS-OUT
A-RTD: UT19.5(Y2) ; off-sheet A-RTD
A-RTD-N: J1.10 LT7.1 ; off-sheet A-RTD-N
A-RTD-N-Filter: CT55.2 LT7.2 RT102.2 UT19.7(B2) ; off-sheet A-RTD-N-Filter
A-RTD-P: J1.9 LT5.1 ; off-sheet A-RTD-P
A-RTD-P-Filter: CT55.1 LT5.2 RT102.1 UT19.6(A2) ; off-sheet A-RTD-P-Filter
AHS-PWM: RB28.1 ; off-sheet AHS-PWM
AHS-PWM-N: J1.4 UT24.3(Z1) ; off-sheet AHS-PWM-N
AHS-PWM-P: J1.3 UT24.2(Y1) ; off-sheet AHS-PWM-P
ALS-PWM: RB29.1 ; off-sheet ALS-PWM
ALS-PWM-N: J1.6 UT24.5(Z2) ; off-sheet ALS-PWM-N
ALS-PWM-P: J1.5 UT24.6(Y2) ; off-sheet ALS-PWM-P
B-FAULT: UT19.11(Y3) ; off-sheet B-FAULT
B-FAULT-N: J2.8 LT8.1 ; off-sheet B-FAULT-N
B-FAULT-N-Filter: CT56.2 LT8.2 RT103.2 UT19.9(B3) ; off-sheet B-FAULT-N-Filter
B-FAULT-P: J2.7 LT6.1 ; off-sheet B-FAULT-P
B-FAULT-P-Filter: CT56.1 LT6.2 RT103.1 UT19.10(A3) ; off-sheet B-FAULT-P-Filter
B-LEN: J2.13 UT22.14(Y5) ; off-sheet B-LEN
B-LEN-OUT: UT22.6(A5) ; off-sheet B-LEN-OUT
B-OCEN: J2.15 UT22.13(Y6) ; off-sheet B-OCEN
B-OCEN-OUT: UT22.7(A6) ; off-sheet B-OCEN-OUT
B-PSDIS: J2.11 UT23.17(Y2) ; off-sheet B-PSDIS
B-PSDIS-OUT: UT23.3(A2) ; off-sheet B-PSDIS-OUT
B-RTD: UT19.13(Y4) ; off-sheet B-RTD
B-RTD-N: J2.10 LT2.1 ; off-sheet B-RTD-N
B-RTD-N-Filter: CT53.2 LT2.2 RT92.2 UT19.15(B4) ; off-sheet B-RTD-N-Filter
B-RTD-P: J2.9 LT4.1 ; off-sheet B-RTD-P
B-RTD-P-Filter: CT53.1 LT4.2 RT92.1 UT19.14(A4) ; off-sheet B-RTD-P-Filter
BHS-PWM: RB30.1 ; off-sheet BHS-PWM
BHS-PWM-N: J2.4 UT24.11(Z3) ; off-sheet BHS-PWM-N
BHS-PWM-P: J2.3 UT24.10(Y3) ; off-sheet BHS-PWM-P
BLS-PWM: RB27.1 ; off-sheet BLS-PWM
BLS-PWM-N: J2.6 UT24.13(Z4) ; off-sheet BLS-PWM-N
BLS-PWM-P: J2.5 UT24.14(Y4) ; off-sheet BLS-PWM-P
C-FAULT: UT20.3(Y1) ; off-sheet C-FAULT
C-FAULT-N: J3.8 LT9.1 ; off-sheet C-FAULT-N
C-FAULT-N-Filter: CT57.2 LT9.2 RT104.2 UT20.1(B1) ; off-sheet C-FAULT-N-Filter
C-FAULT-P: J3.7 LT10.1 ; off-sheet C-FAULT-P
C-FAULT-P-Filter: CT57.1 LT10.2 RT104.1 UT20.2(A1) ; off-sheet C-FAULT-P-Filter
C-LEN: J3.13 UT22.16(Y3) ; off-sheet C-LEN
C-LEN-OUT: UT22.4(A3) ; off-sheet C-LEN-OUT
C-OCEN: J3.15 UT22.15(Y4) ; off-sheet C-OCEN
C-OCEN-OUT: UT22.5(A4) ; off-sheet C-OCEN-OUT
C-PSDIS: J3.11 UT23.18(Y1) ; off-sheet C-PSDIS
C-PSDIS-OUT: UT23.2(A1) ; off-sheet C-PSDIS-OUT
C-RTD: UT20.5(Y2) ; off-sheet C-RTD
C-RTD-N: J3.10 LT12.1 ; off-sheet C-RTD-N
C-RTD-N-Filter: CT58.2 LT12.2 RT105.2 UT20.7(B2) ; off-sheet C-RTD-N-Filter
C-RTD-P: J3.9 LT11.1 ; off-sheet C-RTD-P
C-RTD-P-Filter: CT58.1 LT11.2 RT105.1 UT20.6(A2) ; off-sheet C-RTD-P-Filter
CHS-PWM: RT118.1 ; off-sheet CHS-PWM
CHS-PWM-N: J3.4 UT25.3(Z1) ; off-sheet CHS-PWM-N
CHS-PWM-P: J3.3 UT25.2(Y1) ; off-sheet CHS-PWM-P
CLS-PWM: RT113.1 ; off-sheet CLS-PWM
CLS-PWM-N: J3.6 UT25.5(Z2) ; off-sheet CLS-PWM-N
CLS-PWM-P: J3.5 UT25.6(Y2) ; off-sheet CLS-PWM-P
NetCB20_1: CB20.1 RB27.2 UT24.15(A4)
NetCB21_1: CB21.1 RB28.2 UT24.1(A1)
NetCB22_1: CB22.1 RB30.2 UT24.9(A3)
NetCB23_1: CB23.1 RB29.2 UT24.7(A2)
NetCT64_1: CT64.1 RT113.2 UT25.7(A2)
NetCT67_1: CT67.1 RT118.2 UT25.1(A1)
NetRT89_1: RT89.1 UT20.12(~{G})
NetRT100_2: RT100.2 UT19.4(G)
NetRT101_1: RT101.1 UT19.12(~{G})
NetRT106_2: RT106.2 UT20.4(G)
NetRT111_2: RT111.2 UT25.12(~{EN})
NetRT112_2: RT112.2 UT24.4(EN)
NetRT114_2: RT114.2 UT24.12(~{EN})
NetRT120_2: RT120.2 UT25.4(EN)

Not connected (* = marked no-connect by the designer): UT20 9(B3) 10(A3) 11(Y3) 13(Y4) 14(A4) 15(B4); UT22 17(Y2) 18(Y1); UT23 11(Y8) 12(Y7) 13(Y6) 14(Y5) 15(Y4); UT25 9(A3) 10(Y3) 11(Z3) 13(Z4) 14(Y4) 15(A4)

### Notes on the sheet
- (near UT22) 296-18698-1-ND

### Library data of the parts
*#3 = DualBrandTitleBlock1: as *#1 on sheet CAN
CB20 = CAP: CAP CER 100PF 50V 5% NP0 0603; Part Reference: CB20; PART_NUMBER: TMP-455; Manufacturer: Samsung Electro-Mechanics America, Inc; Manufacturer PN: CL10C101JB8NNNC; Company Part Status: New; Dielectric Type: Capacitors; Temperature Coefficient: C0G, NP0; CLASS: DISCRETE
CB21 = CAP: CAP CER 100PF 50V 5% NP0 0603; Part Reference: CB21; PART_NUMBER: TMP-455; Manufacturer: Samsung Electro-Mechanics America, Inc; Manufacturer PN: CL10C101JB8NNNC; Company Part Status: New; Dielectric Type: Capacitors; Temperature Coefficient: C0G, NP0; CLASS: DISCRETE
CB22 = CAP: CAP CER 100PF 50V 5% NP0 0603; Part Reference: CB22; PART_NUMBER: TMP-455; Manufacturer: Samsung Electro-Mechanics America, Inc; Manufacturer PN: CL10C101JB8NNNC; Company Part Status: New; Dielectric Type: Capacitors; Temperature Coefficient: C0G, NP0; CLASS: DISCRETE
CB23 = CAP: CAP CER 100PF 50V 5% NP0 0603; Part Reference: CB23; PART_NUMBER: TMP-455; Manufacturer: Samsung Electro-Mechanics America, Inc; Manufacturer PN: CL10C101JB8NNNC; Company Part Status: New; Dielectric Type: Capacitors; Temperature Coefficient: C0G, NP0; CLASS: DISCRETE
CT49 = CAP: CAP CER 0.1UF 25V X7R 0603; Part Reference: CT49; Manufacturer PN: C0603C104K3RACTU; Manufacturer: Kemet; PART_NUMBER: TMP-847; Company Part Status: New; CLASS: DISCRETE; Tolerance: 10%; Dielectric Type: Capacitors
CT50 = CAP: CAP CER 0.1UF 25V X7R 0603; Part Reference: CT50; Manufacturer PN: C0603C104K3RACTU; Manufacturer: Kemet; PART_NUMBER: TMP-847; Company Part Status: New; CLASS: DISCRETE; Tolerance: 10%; Dielectric Type: Capacitors
CT52 = CAP: CAP CER 27PF 50V NP0 0603; Part Reference: CT52; PART_NUMBER: TMP-759; Manufacturer: Samsung Electro-Mechanics America, Inc.; Manufacturer PN: CL10C270JB8NNNC; Company Part Status: New; Dielectric Type: Capacitors; Temperature Coefficient: C0G, NP0; Tolerance: 5%; CLASS: DISCRETE
CT53 = CAP: CAP CER 27PF 50V NP0 0603; Part Reference: CT53; PART_NUMBER: TMP-759; Manufacturer: Samsung Electro-Mechanics America, Inc.; Manufacturer PN: CL10C270JB8NNNC; Company Part Status: New; Dielectric Type: Capacitors; Temperature Coefficient: C0G, NP0; Tolerance: 5%; CLASS: DISCRETE
CT55 = CAP: CAP CER 27PF 50V NP0 0603; Part Reference: CT55; PART_NUMBER: TMP-759; Manufacturer: Samsung Electro-Mechanics America, Inc.; Manufacturer PN: CL10C270JB8NNNC; Company Part Status: New; Dielectric Type: Capacitors; Temperature Coefficient: C0G, NP0; Tolerance: 5%; CLASS: DISCRETE
CT56 = CAP: CAP CER 27PF 50V NP0 0603; Part Reference: CT56; PART_NUMBER: TMP-759; Manufacturer: Samsung Electro-Mechanics America, Inc.; Manufacturer PN: CL10C270JB8NNNC; Company Part Status: New; Dielectric Type: Capacitors; Temperature Coefficient: C0G, NP0; Tolerance: 5%; CLASS: DISCRETE
CT57 = CAP: CAP CER 27PF 50V NP0 0603; Part Reference: CT57; PART_NUMBER: TMP-759; Manufacturer: Samsung Electro-Mechanics America, Inc.; Manufacturer PN: CL10C270JB8NNNC; Company Part Status: New; Dielectric Type: Capacitors; Temperature Coefficient: C0G, NP0; Tolerance: 5%; CLASS: DISCRETE
CT58 = CAP: CAP CER 27PF 50V NP0 0603; Part Reference: CT58; PART_NUMBER: TMP-759; Manufacturer: Samsung Electro-Mechanics America, Inc.; Manufacturer PN: CL10C270JB8NNNC; Company Part Status: New; Dielectric Type: Capacitors; Temperature Coefficient: C0G, NP0; Tolerance: 5%; CLASS: DISCRETE
CT60 = CAP: CAP CER 0.1UF 25V X7R 0603; Part Reference: CT60; PART_NUMBER: TMP-847; Manufacturer: Kemet; Manufacturer PN: C0603C104K3RACTU; Company Part Status: New; Dielectric Type: Capacitors; Tolerance: 10%; CLASS: DISCRETE
CT61 = CAP: CAP CER 0.1UF 25V X7R 0603; Part Reference: CT61; PART_NUMBER: TMP-847; Manufacturer: Kemet; Manufacturer PN: C0603C104K3RACTU; Company Part Status: New; Dielectric Type: Capacitors; Tolerance: 10%; CLASS: DISCRETE
CT64 = CAP: CAP CER 100PF 50V 5% NP0 0603; Part Reference: CT64; Manufacturer PN: CL10C101JB8NNNC; Manufacturer: Samsung Electro-Mechanics America, Inc; PART_NUMBER: TMP-455; Company Part Status: New; CLASS: DISCRETE; Temperature Coefficient: C0G, NP0; Dielectric Type: Capacitors
CT65 = CAP: CAP CER 0.1UF 25V X7R 0603; Part Reference: CT65; Manufacturer PN: C0603C104K3RACTU; Manufacturer: Kemet; PART_NUMBER: TMP-847; Company Part Status: New; CLASS: DISCRETE; Tolerance: 10%; Dielectric Type: Capacitors
CT66 = CAP: CAP CER 0.1UF 25V X7R 0603; Part Reference: CT66; PART_NUMBER: TMP-847; Manufacturer: Kemet; Manufacturer PN: C0603C104K3RACTU; Company Part Status: New; Dielectric Type: Capacitors; Tolerance: 10%; CLASS: DISCRETE
CT67 = CAP: CAP CER 100PF 50V 5% NP0 0603; Part Reference: CT67; Manufacturer PN: CL10C101JB8NNNC; Manufacturer: Samsung Electro-Mechanics America, Inc; PART_NUMBER: TMP-455; Company Part Status: New; CLASS: DISCRETE; Temperature Coefficient: C0G, NP0; Dielectric Type: Capacitors
J1 = CON16A_Corrected: CONN HEADER 2.54MM 16POS GOLD; Part Reference: J1; PART_NUMBER: TMP-739; Manufacturer: Sullins Connector Solutions; Company Part Status: New; CLASS: IO
J2 = CON16A_Corrected: CONN HEADER 2.54MM 16POS GOLD; Part Reference: J2; PART_NUMBER: TMP-739; Manufacturer: Sullins Connector Solutions; Company Part Status: New; CLASS: IO
J3 = CON16A_Corrected: CONN HEADER 2.54MM 16POS GOLD; Part Reference: J3; PART_NUMBER: TMP-739; Manufacturer: Sullins Connector Solutions; Company Part Status: New; CLASS: IO
LT1 = INDUCTOR: FIXED IND 1UH 1.15A 60 MOHM SMD; Part Reference: LT1; Manufacturer PN: MLZ2012N1R0LT000; Manufacturer: TDK Corporation; PART_NUMBER: TMP-610; Company Part Status: New; CLASS: DISCRETE; Tolerance: 20%
LT2 = INDUCTOR: FIXED IND 1UH 1.15A 60 MOHM SMD; Part Reference: LT2; Manufacturer PN: MLZ2012N1R0LT000; Manufacturer: TDK Corporation; PART_NUMBER: TMP-610; Company Part Status: New; CLASS: DISCRETE; Tolerance: 20%
LT3 = INDUCTOR: FIXED IND 1UH 1.15A 60 MOHM SMD; Part Reference: LT3; Manufacturer PN: MLZ2012N1R0LT000; Manufacturer: TDK Corporation; PART_NUMBER: TMP-610; Company Part Status: New; CLASS: DISCRETE; Tolerance: 20%
LT4 = INDUCTOR: FIXED IND 1UH 1.15A 60 MOHM SMD; Part Reference: LT4; Manufacturer PN: MLZ2012N1R0LT000; Manufacturer: TDK Corporation; PART_NUMBER: TMP-610; Company Part Status: New; CLASS: DISCRETE; Tolerance: 20%
LT5 = INDUCTOR: FIXED IND 1UH 1.15A 60 MOHM SMD; Part Reference: LT5; Manufacturer PN: MLZ2012N1R0LT000; Manufacturer: TDK Corporation; PART_NUMBER: TMP-610; Company Part Status: New; CLASS: DISCRETE; Tolerance: 20%
LT6 = INDUCTOR: FIXED IND 1UH 1.15A 60 MOHM SMD; Part Reference: LT6; Manufacturer PN: MLZ2012N1R0LT000; Manufacturer: TDK Corporation; PART_NUMBER: TMP-610; Company Part Status: New; CLASS: DISCRETE; Tolerance: 20%
LT7 = INDUCTOR: FIXED IND 1UH 1.15A 60 MOHM SMD; Part Reference: LT7; Manufacturer PN: MLZ2012N1R0LT000; Manufacturer: TDK Corporation; PART_NUMBER: TMP-610; Company Part Status: New; CLASS: DISCRETE; Tolerance: 20%
LT8 = INDUCTOR: FIXED IND 1UH 1.15A 60 MOHM SMD; Part Reference: LT8; Manufacturer PN: MLZ2012N1R0LT000; Manufacturer: TDK Corporation; PART_NUMBER: TMP-610; Company Part Status: New; CLASS: DISCRETE; Tolerance: 20%
LT9 = INDUCTOR: FIXED IND 1UH 1.15A 60 MOHM SMD; Part Reference: LT9; Manufacturer PN: MLZ2012N1R0LT000; Manufacturer: TDK Corporation; PART_NUMBER: TMP-610; Company Part Status: New; CLASS: DISCRETE; Tolerance: 20%
LT10 = INDUCTOR: FIXED IND 1UH 1.15A 60 MOHM SMD; Part Reference: LT10; Manufacturer PN: MLZ2012N1R0LT000; Manufacturer: TDK Corporation; PART_NUMBER: TMP-610; Company Part Status: New; CLASS: DISCRETE; Tolerance: 20%
LT11 = INDUCTOR: FIXED IND 1UH 1.15A 60 MOHM SMD; Part Reference: LT11; Manufacturer PN: MLZ2012N1R0LT000; Manufacturer: TDK Corporation; PART_NUMBER: TMP-610; Company Part Status: New; CLASS: DISCRETE; Tolerance: 20%
LT12 = INDUCTOR: FIXED IND 1UH 1.15A 60 MOHM SMD; Part Reference: LT12; Manufacturer PN: MLZ2012N1R0LT000; Manufacturer: TDK Corporation; PART_NUMBER: TMP-610; Company Part Status: New; CLASS: DISCRETE; Tolerance: 20%
RB27 = R: RES SMD 120 OHM 5% 1/10W 0603; Part Reference: RB27; Manufacturer PN: RC0603JR-07120RL; Manufacturer: Yageo; PART_NUMBER: TMP-619; Company Part Status: New; CLASS: DISCRETE; Rated Power: 0.1W, 1/10W; Temperature Coefficient: 100ppm/C
RB28 = R: RES SMD 120 OHM 5% 1/10W 0603; Part Reference: RB28; PART_NUMBER: TMP-619; Manufacturer: Yageo; Manufacturer PN: RC0603JR-07120RL; Company Part Status: New; Temperature Coefficient: 100ppm/C; Rated Power: 0.1W, 1/10W; CLASS: DISCRETE
RB29 = R: RES SMD 120 OHM 5% 1/10W 0603; Part Reference: RB29; Manufacturer PN: RC0603JR-07120RL; Manufacturer: Yageo; PART_NUMBER: TMP-619; Company Part Status: New; CLASS: DISCRETE; Rated Power: 0.1W, 1/10W; Temperature Coefficient: 100ppm/C
RB30 = R: RES SMD 120 OHM 5% 1/10W 0603; Part Reference: RB30; Manufacturer PN: RC0603JR-07120RL; Manufacturer: Yageo; PART_NUMBER: TMP-619; Company Part Status: New; CLASS: DISCRETE; Rated Power: 0.1W, 1/10W; Temperature Coefficient: 100ppm/C
RT89 = R: RES SMD 15K OHM 5% 1/10W 0603; Part Reference: RT89; Manufacturer PN: RC0603JR-0715KL; Manufacturer: Yageo; PART_NUMBER: TMP-618; Company Part Status: New; CLASS: DISCRETE; Rated Power: 0.1W, 1/10W; Temperature Coefficient: 100ppm/C
RT91 = RES_Dup1: RES SMD 100 OHM 1% 1/10W 0603; Part Reference: RT91; Manufacturer PN: RC0603FR-07100RL; Manufacturer: Yageo; PART_NUMBER: TMP-865; Company Part Status: New; CLASS: DISCRETE; Rated Power: 0.1W, 1/10W; Temperature Coefficient: 100ppm/C
RT92 = RES_Dup1: RES SMD 100 OHM 1% 1/10W 0603; Part Reference: RT92; Manufacturer PN: RC0603FR-07100RL; Manufacturer: Yageo; PART_NUMBER: TMP-865; Company Part Status: New; CLASS: DISCRETE; Rated Power: 0.1W, 1/10W; Temperature Coefficient: 100ppm/C
RT100 = R: RES SMD 15K OHM 5% 1/10W 0603; Part Reference: RT100; Manufacturer PN: RC0603JR-0715KL; Manufacturer: Yageo; PART_NUMBER: TMP-618; Company Part Status: New; CLASS: DISCRETE; Rated Power: 0.1W, 1/10W; Temperature Coefficient: 100ppm/C
RT101 = R: RES SMD 15K OHM 5% 1/10W 0603; Part Reference: RT101; Manufacturer PN: RC0603JR-0715KL; Manufacturer: Yageo; PART_NUMBER: TMP-618; Company Part Status: New; CLASS: DISCRETE; Rated Power: 0.1W, 1/10W; Temperature Coefficient: 100ppm/C
RT102 = RES_Dup1: RES SMD 100 OHM 1% 1/10W 0603; Part Reference: RT102; Manufacturer PN: RC0603FR-07100RL; Manufacturer: Yageo; PART_NUMBER: TMP-865; Company Part Status: New; CLASS: DISCRETE; Rated Power: 0.1W, 1/10W; Temperature Coefficient: 100ppm/C
RT103 = RES_Dup1: RES SMD 100 OHM 1% 1/10W 0603; Part Reference: RT103; Manufacturer PN: RC0603FR-07100RL; Manufacturer: Yageo; PART_NUMBER: TMP-865; Company Part Status: New; CLASS: DISCRETE; Rated Power: 0.1W, 1/10W; Temperature Coefficient: 100ppm/C
RT104 = RES_Dup1: RES SMD 100 OHM 1% 1/10W 0603; Part Reference: RT104; Manufacturer PN: RC0603FR-07100RL; Manufacturer: Yageo; PART_NUMBER: TMP-865; Company Part Status: New; CLASS: DISCRETE; Rated Power: 0.1W, 1/10W; Temperature Coefficient: 100ppm/C
RT105 = RES_Dup1: RES SMD 100 OHM 1% 1/10W 0603; Part Reference: RT105; Manufacturer PN: RC0603FR-07100RL; Manufacturer: Yageo; PART_NUMBER: TMP-865; Company Part Status: New; CLASS: DISCRETE; Rated Power: 0.1W, 1/10W; Temperature Coefficient: 100ppm/C
RT106 = R: RES SMD 15K OHM 5% 1/10W 0603; Part Reference: RT106; Manufacturer PN: RC0603JR-0715KL; Manufacturer: Yageo; PART_NUMBER: TMP-618; Company Part Status: New; CLASS: DISCRETE; Rated Power: 0.1W, 1/10W; Temperature Coefficient: 100ppm/C
RT111 = R: RES SMD 15K OHM 5% 1/10W 0603; Part Reference: RT111; PART_NUMBER: TMP-618; Manufacturer: Yageo; Manufacturer PN: RC0603JR-0715KL; Company Part Status: New; Temperature Coefficient: 100ppm/C; Rated Power: 0.1W, 1/10W; CLASS: DISCRETE
RT112 = R: RES SMD 15K OHM 5% 1/10W 0603; Part Reference: RT112; PART_NUMBER: TMP-618; Manufacturer: Yageo; Manufacturer PN: RC0603JR-0715KL; Company Part Status: New; Temperature Coefficient: 100ppm/C; Rated Power: 0.1W, 1/10W; CLASS: DISCRETE
RT113 = R: RES SMD 120 OHM 5% 1/10W 0603; Part Reference: RT113; PART_NUMBER: TMP-619; Manufacturer: Yageo; Manufacturer PN: RC0603JR-07120RL; Company Part Status: New; Temperature Coefficient: 100ppm/C; Rated Power: 0.1W, 1/10W; CLASS: DISCRETE
RT114 = R: RES SMD 15K OHM 5% 1/10W 0603; Part Reference: RT114; Manufacturer PN: RC0603JR-0715KL; Manufacturer: Yageo; PART_NUMBER: TMP-618; Company Part Status: New; CLASS: DISCRETE; Rated Power: 0.1W, 1/10W; Temperature Coefficient: 100ppm/C
RT118 = R: RES SMD 120 OHM 5% 1/10W 0603; Part Reference: RT118; Manufacturer PN: RC0603JR-07120RL; Manufacturer: Yageo; PART_NUMBER: TMP-619; Company Part Status: New; CLASS: DISCRETE; Rated Power: 0.1W, 1/10W; Temperature Coefficient: 100ppm/C
RT120 = R: RES SMD 15K OHM 5% 1/10W 0603; Part Reference: RT120; Manufacturer PN: RC0603JR-0715KL; Manufacturer: Yageo; PART_NUMBER: TMP-618; Company Part Status: New; CLASS: DISCRETE; Rated Power: 0.1W, 1/10W; Temperature Coefficient: 100ppm/C
UT19 = DIFFRCVR_4XG_16P: IC RCVR DIFF QUAD LV HS 16TSSOP; Part Reference: UT19; Manufacturer: Texas Instruments; Company Part Status: New; Supply Voltage: 3 V - 3.6 V
UT20 = DIFFRCVR_4XG_16P: IC RCVR DIFF QUAD LV HS 16TSSOP; Part Reference: UT20; Manufacturer: Texas Instruments; Company Part Status: New; Supply Voltage: 3 V - 3.6 V
UT22 = 74-541_20P_Dup1: IC BUF NON-INVERT 5.5V 20TSSOP; Part Reference: UT22; Manufacturer: Texas Instruments; Company Part Status: New; Supply Voltage: 4.5 V - 5.5 V
UT23 = 74-541_20P: IC BUF NON-INVERT 5.5V 20TSSOP; Part Reference: UT23; Manufacturer: Texas Instruments; Company Part Status: New; Supply Voltage: 4.5 V - 5.5 V
UT24 = DIFFDRVR_4X_16P: IC DVR DIFF QUAD LV HS 16TSSOP; Part Reference: UT24; Manufacturer: Texas Instruments; Company Part Status: New; Supply Voltage: 3 V - 3.6 V
UT25 = DIFFDRVR_4X_16P: IC DVR DIFF QUAD LV HS 16TSSOP; Part Reference: UT25; Manufacturer: Texas Instruments; Company Part Status: New; Supply Voltage: 3 V - 3.6 V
